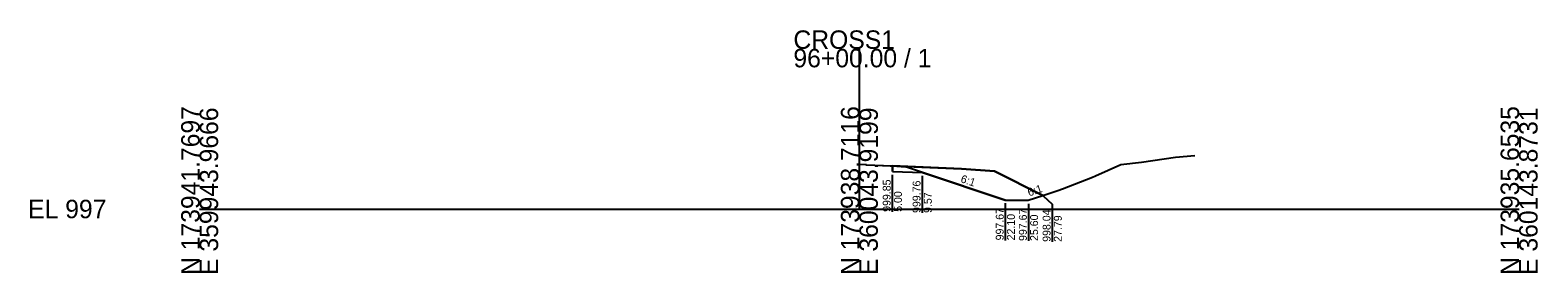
# Model space of a CAD drawing. Extents: x -26 to 1403, y -10 to 11027.
# Drawn here: x -25.7 to 202.8, y 10990.3 to 11027.1 of the extents above; entities that cross this region are included whole.
import ezdxf

# ---------------------------------------------------------------- set-up
doc = ezdxf.new("R2010")
doc.units = 0
for name, color, linetype in [('Default', 7, 'Continuous'), ('P_E_XS_Ground', 7, 'Continuous'), ('P_XS', 7, 'Continuous'), ('P_XS_EAR_CommonGrnd', 7, 'Continuous'), ('P_XS_Lane', 7, 'Continuous'), ('P_XS_Rock', 7, 'Continuous')]:
    doc.layers.add(name, color=color, linetype=linetype)

msp = doc.modelspace()

# ---------------------------------------------------------------- linework, layer by layer
at = {"layer": 'Default'}
for p, q in [((100, 11000), (100, 11024.3)), ((0, 11000), (100, 11000)), ((100, 11000), (200, 11000))]:
    msp.add_line(p, q, dxfattribs=at)
at = {"layer": 'P_E_XS_Ground'}
for p, q in [((101.08, 11006.7), (99.71, 11006.75)), ((101.08, 11006.7), (115.5, 11006.12)), ((135.81, 11005.02), (139.61, 11006.75)), ((139.61, 11006.75), (142.75, 11007.09)), ((142.75, 11007.09), (147.93, 11007.89)), ((147.93, 11007.89), (150.86, 11008.1)), ((115.5, 11006.12), (120.5, 11005.72)), ((120.5, 11005.72), (127.79, 11002.07)), ((130.81, 11003.06), (135.33, 11004.82)), ((135.33, 11004.82), (135.81, 11005.02)), ((127.79, 11002.07), (130.08, 11002.83)), ((130.08, 11002.83), (130.81, 11003.06))]:
    msp.add_line(p, q, dxfattribs=at)
at = {"layer": 'P_XS'}
for p, q in [((101, 11006.7), (105, 11006.54)), ((105, 11006.54), (107, 11006.38)), ((109.57, 11005.52), (107, 11006.38))]:
    msp.add_line(p, q, dxfattribs=at)
at = {"layer": 'P_XS_EAR_CommonGrnd'}
msp.add_lwpolyline([(105, 11005.71), (109.57, 11005.52), (122.1, 11001.34), (125.6, 11001.34), (127.79, 11002.07), (120.5, 11005.72), (115.5, 11006.12), (105, 11006.54)], close=True, dxfattribs=at)
at = {"layer": 'P_XS_Lane'}
for p, q in [((105, 11005.71), (105, 11006.54)), ((105, 11005.71), (109.57, 11005.52)), ((122.1, 11001.34), (109.57, 11005.52)), ((125.6, 11001.34), (127.79, 11002.07)), ((122.1, 11001.34), (125.6, 11001.34))]:
    msp.add_line(p, q, dxfattribs=at)
at = {"layer": 'P_XS_Rock'}
for p, q in [((104.99, 11005.2), (104.99, 10999.57)), ((109.52, 11005.03), (109.52, 10999.4)), ((127.88, 11001.99), (129.23, 11000.73)), ((122.12, 11000.86), (122.12, 10995.24)), ((125.63, 11000.77), (125.63, 10995.15)), ((129.23, 11000.73), (129.23, 10995.02))]:
    msp.add_line(p, q, dxfattribs=at)

# ---------------------------------------------------------------- texts
at = {"layer": 'Default'}
for s, p in [('CROSS1', (90, 11024.3)), ('96+00.00 / 1', (90, 11021.5)), ('EL 997', (-26, 10998.6))]:
    msp.add_text(s, height=2.8, dxfattribs=at).set_placement(p)
for s, p in [('N 173941.7697', (0, 10990)), ('N 173938.7116', (100, 10990)), ('N 173935.6535', (200, 10990)), ('E 359943.9666', (2.8, 10990)), ('E 360043.9199', (102.8, 10990)), ('E 360143.8731', (202.8, 10990))]:
    msp.add_text(s, height=2.8, rotation=90, dxfattribs=at).set_placement(p)
at = {"layer": 'P_XS_Rock'}
for s, rotation, p in [('999.85', 90, (104.74, 10999.57)), ('999.76', 90, (109.27, 10999.4)), ('6:1', 341.5651, (115.25, 11004.09)), ('5.00', 90, (106.44, 10999.57)), ('9.57', 90, (110.97, 10999.4)), ('6:1', 18.4349, (125.73, 11001.9)), ('997.67', 90, (121.87, 10995.24)), ('997.67', 90, (125.38, 10995.15)), ('998.04', 90, (128.98, 10995.02)), ('22.10', 90, (123.57, 10995.24)), ('25.60', 90, (127.08, 10995.15)), ('27.79', 90, (130.68, 10995.02))]:
    msp.add_text(s, height=1.2, rotation=rotation, dxfattribs=at).set_placement(p)

doc.saveas('drawing.dxf')
